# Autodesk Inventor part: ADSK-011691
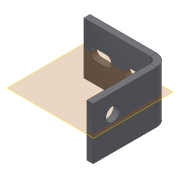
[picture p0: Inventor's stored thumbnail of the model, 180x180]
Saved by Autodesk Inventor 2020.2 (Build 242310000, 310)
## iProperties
Created: 2000-02
Part Number: ADSK-011691
Document SubType Name: Blech
Designer: sspink
Material: 1.0312 DC05
Density: 1 g/cm^3
Sheet Metal Rule: Stahlblech 1.0312 - DC05 -   6.0 mm
Appearance: Metal-Steel(Polish)
Mass: 38.5832 g
Surface Area: 160.21 cm^2
Volume: 38.5832 cm^3
Flat Pattern Width: 5 cm
Flat Pattern Length: 13.8572 cm
Flat Pattern Area: 69.2858 cm^2
Sheet Metal Width: 50,000 mm
Sheet Metal Length: 138,572 mm
Sheet Metal Area: 6928,584 mm^2
Control State: 0
Checked Out: False
Master: False
Shininess: 25.0
Length Units: 11269
Angle Units: 11279
Time Units: 11290
Mass Units: 11283
Length Display Precision: 3
Angle Display Precision: 2
Compacted: True
Cutlength: 704 SI (20.25 X 34.75)
Material Desc: SHEET,HRS,11 GA
Material_Number: Axxxxxx
Dimensions: 50x73x76 mm
Mass: 0,039 kg
Semi finished: Stahlblech 1.0312 - DC05 -   6.0 mm
VLT_Material: 1.0312 DC05
G_L: 50x138,6 mm
Thickness: 6,000 mm
Density: 7.830000000000001
Volumn: 12.290298000000002
Area: 85.48370000000003
PropertySet Name: Model Information
Author: sspink
Revision Number: -
Title: ADSK-011691
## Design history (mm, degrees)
node "Face1"
  sketch "Sketch1"
    geometry: L1 (0, 0)-(76, 0); L2 (76, 0)-(76, 50); L3 (76, 50)-(0, 50); L4 (0, 50)-(0, 0)
    constraints: 8 end point, 2 parallel, 1 horizontal, 1 perpendicular
    dimensions: "d0" = 50 distance between parallel lines of L1 L3; "d1" = 76 distance between parallel lines of L2 L4
node "Lasche2"
node "Hole1" dims "d6" = 13.5, "d7" = 9.525, "d8" = 6.35, "d9" = 60 deg, "d10" = 19.05, "d11" = 118 deg, "d39" = 6
  sketch "Sketch3"
    geometry: L1 (-0.15, 0)-(-0.15, 50) reference; L2 (-0.15, 50)-(60.85, 50) reference; 1 further point
    dimensions: "d37" = 19 distance from line of L1 point (18.85, 32); "d38" = 18 distance from line of point (18.85, 32) L2
node "Cut1" dims "d16" = 6 (= Thickness), "d17" = 0
  sketch "Sketch4" dims "d26" = 6 (= Thickness)
    geometry: L1 (0, 0)-(0, 50) reference; L2 (53.5, 30.25)-(43.5, 30.25); L3 (43.5, 30.25)-(43.5, 19.75); L4 (43.5, 19.75)-(53.5, 19.75); L5 (53.5, 19.75)-(53.5, 30.25); A1 r 5.25 centre (53.5, 25) between (53.5, 19.75) and (53.5, 30.25); A2 r 5.25 centre (43.5, 25) between (43.5, 30.25) and (43.5, 19.75); 2 further points
    constraints: 8 end point, 4 point on circle, 2 centre point, 2 midpoint, 2 parallel, 2 tangent, 1 horizontal, 1 horizontal alignment, 1 perpendicular
    dimensions: "d12" = 10.5 distance between parallel lines of L4 L2; "d13" = 10 distance of L2.start L2.end; "d40" = 43.5 distance between parallel lines of L1 L3
node "Rectangular Pattern1" dims "d18" = 20, "d20" = 32
workplane "Arbeitsebene1"
node "Solide1"
node "Corps solides"
node "Corps surfaciques"
node "Plate1" dims "d26" = 6 (= Thickness)
sketch "Skizze5"
  geometry: L1 through (-25, 0) direction (1, 1.09e-32); L2 through (0, 36.5) direction (-2.16e-32, 1); L3 (0, 73)-(-50, 73); L4 (-50, 73)-(-50, 0)
  constraints: 6 end point, 1 horizontal, 1 perpendicular, 1 vertical
feature "Grobblech3" dims "d26" = 6 (= Thickness), "d27" = 6 (= BendReliefWidth), "d28" = 3 (= BendReliefDepth), "d29" = 12 (= MinimumRemnant), "d30" = 6 (= TransitionRadius), "d31" = 73, "d32" = 90 deg, "d33" = 6 (= BendRadius), "d34" = 24 (= CornerReliefSize), "d35" = 6 (= TailleJeu), "d36" = 6 (= TailleRayonJacobi), "SeamGap" = 0.00508
feature "Biegung2" dims "d26" = 6 (= Thickness), "d27" = 6 (= BendReliefWidth), "d28" = 3 (= BendReliefDepth), "d29" = 12 (= MinimumRemnant), "d30" = 6 (= TransitionRadius), "d31" = 73, "d32" = 90 deg, "d33" = 6 (= BendRadius), "SeamGap" = 0.00508
feature "Ecke1" dims "d31" = 73, "d32" = 90 deg, "d34" = 24 (= CornerReliefSize), "d35" = 6 (= TailleJeu), "d36" = 6 (= TailleRayonJacobi)
feature "Definition1"
other parameters: "Thickness" = 6 (derived), "BendRadius" = 6 (= Thickness), "BendReliefWidth" = 6 (= Thickness), "BendReliefDepth" = 3 (= 0.5 x Thickness), "CornerReliefSize" = 24 (= 4 x Thickness), "MinimumRemnant" = 12 (= 2 x Thickness), "d2" = 6 (= BendRadius), "d3" = 63.5, "d4" = 90 deg, "d5" = 6 (= BendRadius), "TransitionRadius" = 6 (= BendRadius), "TailleRayonJacobi" = 6 (= BendRadius), "TailleJeu" = 6 (= Thickness), "KFaktor" = 4.4, "BendRadius" = 6, "BendReliefDepth" = 3, "BendReliefWidth" = 6, "CornerReliefSize" = 24, "MinimumRemnant" = 12, "TailleJeu" = 6, "TailleRayonJacobi" = 6, "Thickness" = 6, "TransitionRadius" = 6
